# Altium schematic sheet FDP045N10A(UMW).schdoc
size 127 x 101 mm
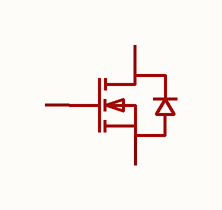
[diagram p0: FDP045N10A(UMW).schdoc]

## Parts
Q?  fdp045n10a(umw)  [TO-220-3_L9.9-W4.5-P2.54-L]  (value not drawn)

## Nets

Not connected (* = marked no-connect by the designer): Q? 1(G) 2(D) 3(S)

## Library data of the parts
Q? = fdp045n10a(umw): 数量:1个N沟道;漏源电压(Vdss):100V;连续漏极电流(Id):164A;导通电阻(RDS(on)):4.5mΩ@10V;耗散功率(Pd):263W;阈值电压(Vgs(th)):4V@250uA;; Manufacturer: UMW(友台半导体); AddInBom: yes; ModelId: 61b625ab855b4726be53be943295af7a; ModelTransform: 389.763,177.165,0,0,0,0,0,6.693,-118.11; Number: 1个N沟道; Drain to Source Voltage: 100V; Current - Continuous Drain(Id): 164A; Pd - Power Dissipation: 263W; Gate Charge(Qg): 74nC@10V; Input Capacitance(Ciss): 5.27nF; Reverse Transfer Capacitance (Crss@Vds): 34pF; Type: N沟道; Output Capacitance(Coss): 1.23nF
